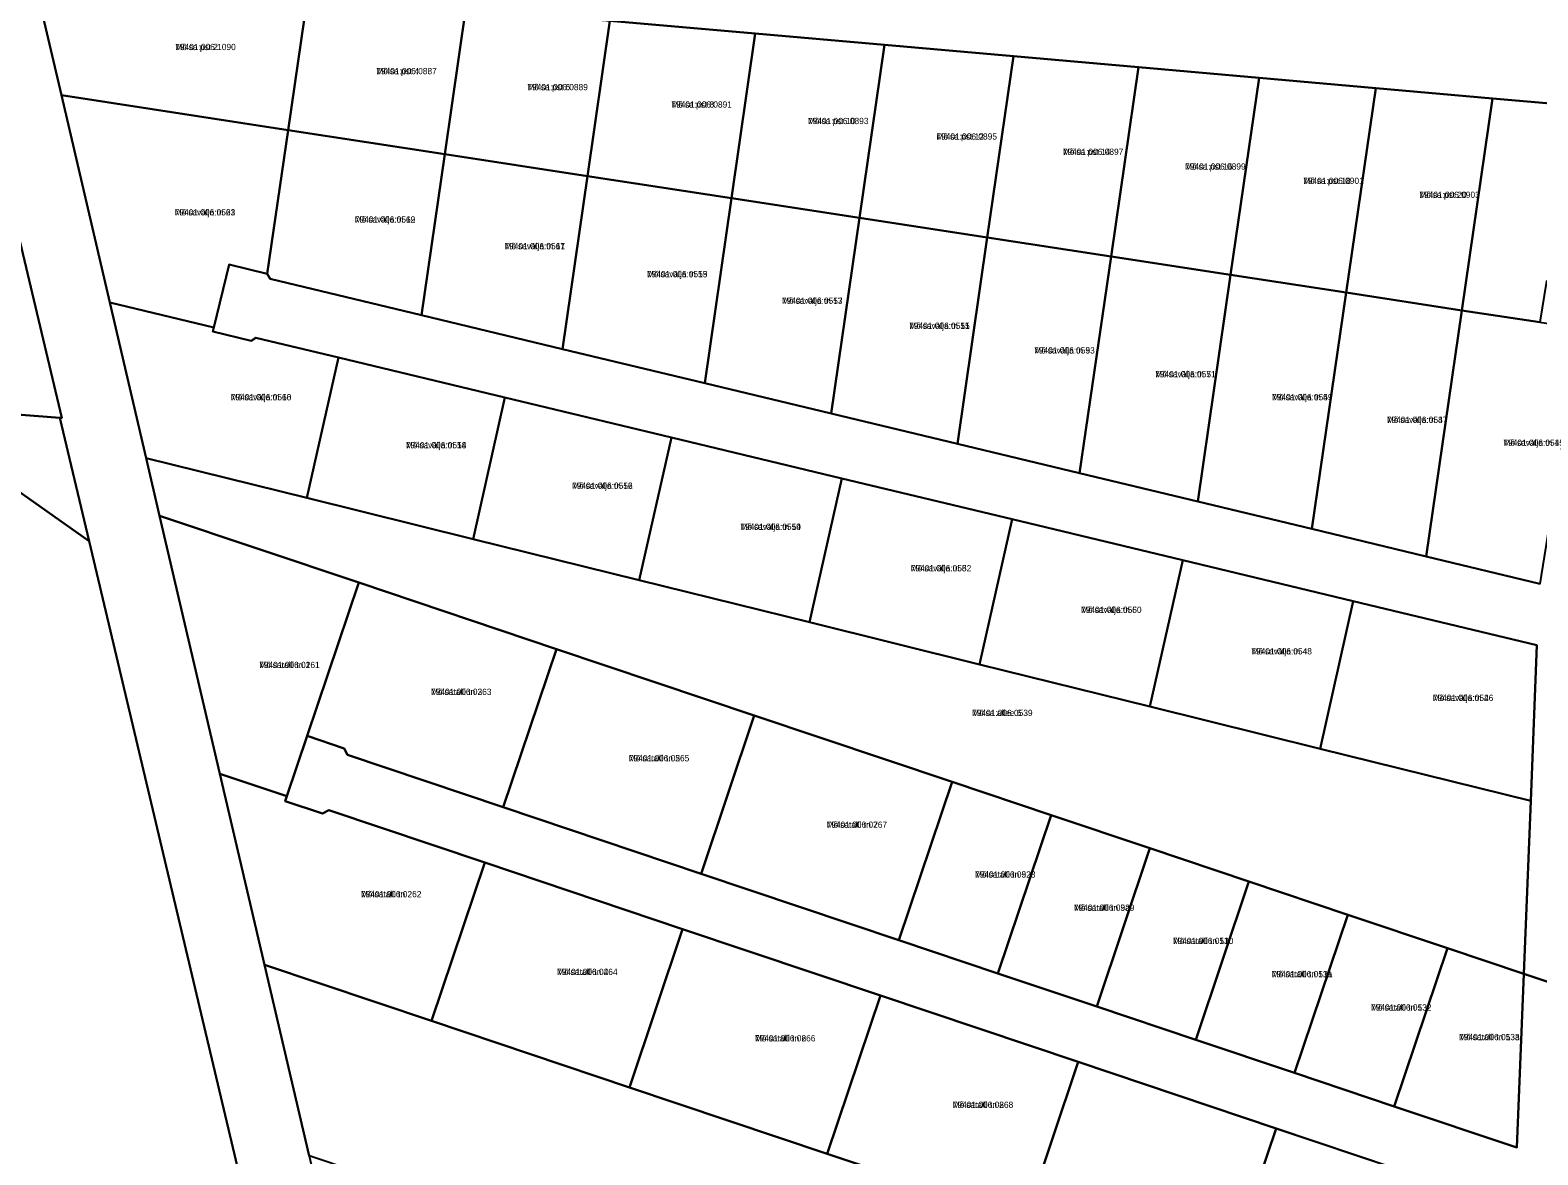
# Model space of a CAD drawing. Extents: x 625111 to 706696, y 6474150 to 6504223.
# Drawn here: x 659027.1 to 659388.4, y 6476981 to 6477250.5 of the extents above; entities that cross this region are included whole.
import ezdxf

# ---------------------------------------------------------------- set-up
doc = ezdxf.new("R2010")
doc.units = 0
for name, color, linetype in [('L_AADRESS', 7, 'Continuous'), ('PIIR', 7, 'Continuous'), ('TUNNUS', 7, 'Continuous')]:
    doc.layers.add(name, color=color, linetype=linetype)

msp = doc.modelspace()

# ---------------------------------------------------------------- linework, layer by layer
at = {"layer": 'PIIR'}
for points in [[(658929.46, 6477515.88), (658932.08, 6477516.4), (658982.24, 6477363.23), (658997.92, 6477309.95), (659008.22, 6477269.11), (659034.75, 6477157.58), (659034.25, 6477157.62), (659022.98, 6477158.48), (659018.49, 6477177.34), (659008.59, 6477218.73), (658996.7, 6477269.62), (658989.31, 6477301.21), (658978.46, 6477340.07), (658976.43, 6477347.36), (658971.21, 6477364.81), (658970.92, 6477365.75), (658960.91, 6477395.57), (658954.44, 6477414.91), (658943.03, 6477449.01), (658921.35, 6477514.3)], [(659093.63, 6477259.08), (659088.92, 6477226.55), (659034.62, 6477234.89), (659027.61, 6477264.87), (659060.39, 6477262)], [(659131.55, 6477255.75), (659126.48, 6477220.78), (659088.92, 6477226.55), (659093.63, 6477259.08)], [(659166.04, 6477252.72), (659160.66, 6477215.53), (659126.48, 6477220.78), (659131.55, 6477255.75)], [(659200.88, 6477249.65), (659195.17, 6477210.23), (659160.66, 6477215.53), (659166.04, 6477252.72)], [(659231.81, 6477246.94), (659225.81, 6477205.53), (659195.17, 6477210.23), (659200.88, 6477249.65)], [(659262.74, 6477244.22), (659256.45, 6477200.82), (659225.81, 6477205.53), (659231.81, 6477246.94)], [(659292.67, 6477241.59), (659286.11, 6477196.27), (659256.45, 6477200.82), (659262.74, 6477244.22)], [(659321.6, 6477239.04), (659314.77, 6477191.86), (659286.11, 6477196.27), (659292.67, 6477241.59)], [(659349.54, 6477236.59), (659342.45, 6477187.61), (659314.77, 6477191.86), (659321.6, 6477239.04)], [(659088.92, 6477226.55), (659083.94, 6477192.1), (659074.78, 6477194.31), (659071.17, 6477179.22), (659046.22, 6477185.21), (659034.62, 6477234.89)], [(659377.48, 6477234.13), (659370.13, 6477183.36), (659342.45, 6477187.61), (659349.54, 6477236.59)], [(659407.08, 6477231.53), (659400.24, 6477188.86), (659390.43, 6477190.36), (659388.85, 6477180.49), (659370.13, 6477183.36), (659377.48, 6477234.13)], [(659126.48, 6477220.78), (659120.9, 6477182.2), (659084.64, 6477190.9), (659083.94, 6477192.1), (659088.92, 6477226.55)], [(659160.66, 6477215.53), (659154.66, 6477174.09), (659120.9, 6477182.2), (659126.48, 6477220.78)], [(659195.17, 6477210.23), (659188.75, 6477165.91), (659154.66, 6477174.09), (659160.66, 6477215.53)], [(659225.81, 6477205.53), (659219.02, 6477158.64), (659188.75, 6477165.91), (659195.17, 6477210.23)], [(659256.45, 6477200.82), (659249.3, 6477151.38), (659219.02, 6477158.64), (659225.81, 6477205.53)], [(658404.01, 6477187.04), (658405.42, 6477203), (658447.18, 6477199.93), (658486.87, 6477196.96), (658527.12, 6477193.96), (658534.1, 6477193.43), (658545.15, 6477192.65), (658686.78, 6477182.82), (658692, 6477182.49), (658697.98, 6477182), (659022.98, 6477158.48), (659034.25, 6477157.62), (659041.31, 6477128.02), (659009.66, 6477150.34), (658694.91, 6477173.6), (658542.28, 6477178.48), (658526.7, 6477177.95)], [(659286.11, 6477196.27), (659278.59, 6477144.34), (659249.3, 6477151.38), (659256.45, 6477200.82)], [(659314.77, 6477191.86), (659306.91, 6477137.55), (659278.59, 6477144.34), (659286.11, 6477196.27)], [(659342.45, 6477187.61), (659334.25, 6477130.98), (659306.91, 6477137.55), (659314.77, 6477191.86)], [(659370.13, 6477183.36), (659361.59, 6477124.42), (659334.25, 6477130.98), (659342.45, 6477187.61)], [(659101.02, 6477172.06), (659093.46, 6477138.41), (659054.92, 6477147.94), (659046.22, 6477185.21), (659071.17, 6477179.22), (659070.94, 6477178.26), (659080.12, 6477176.09), (659081.22, 6477176.81)], [(659398.66, 6477178.98), (659388.87, 6477117.87), (659361.59, 6477124.42), (659370.13, 6477183.36), (659388.85, 6477180.49)], [(659140.89, 6477162.49), (659133.26, 6477128.56), (659093.46, 6477138.41), (659101.02, 6477172.06)], [(659180.76, 6477152.92), (659173.07, 6477118.71), (659133.26, 6477128.56), (659140.89, 6477162.49)], [(659221.6, 6477143.11), (659213.85, 6477108.61), (659173.07, 6477118.71), (659180.76, 6477152.92)], [(659386.69, 6477065.84), (659385.04, 6477024.38), (659366.7, 6477030.54), (659342.83, 6477038.56), (659319.13, 6477046.52), (659295.43, 6477054.47), (659271.73, 6477062.43), (659248.03, 6477070.39), (659200.63, 6477086.3), (659153.23, 6477102.22), (659105.87, 6477118.12), (659058.14, 6477134.15), (659054.92, 6477147.94), (659093.46, 6477138.41), (659133.26, 6477128.56), (659173.07, 6477118.71), (659213.85, 6477108.61), (659254.63, 6477098.52), (659295.41, 6477088.43), (659336.19, 6477078.34)], [(659262.45, 6477133.31), (659254.63, 6477098.52), (659213.85, 6477108.61), (659221.6, 6477143.11)], [(659105.87, 6477118.12), (659093.5, 6477081.41), (659088.6, 6477066.96), (659072.57, 6477072.34), (659058.14, 6477134.15)], [(659303.29, 6477123.5), (659295.41, 6477088.43), (659254.63, 6477098.52), (659262.45, 6477133.31)], [(659344.14, 6477113.7), (659336.19, 6477078.34), (659295.41, 6477088.43), (659303.29, 6477123.5)], [(659153.23, 6477102.22), (659140.5, 6477064.3), (659103.13, 6477076.85), (659102.39, 6477078.42), (659093.5, 6477081.41), (659105.87, 6477118.12)], [(659388.17, 6477103.13), (659386.69, 6477065.84), (659336.19, 6477078.34), (659344.14, 6477113.7)], [(659200.63, 6477086.3), (659187.9, 6477048.38), (659140.5, 6477064.3), (659153.23, 6477102.22)], [(659248.03, 6477070.39), (659235.3, 6477032.47), (659187.9, 6477048.38), (659200.63, 6477086.3)], [(659136.05, 6477051.03), (659123.31, 6477013.11), (659083.27, 6477026.56), (659072.57, 6477072.34), (659088.6, 6477066.96), (659088.21, 6477065.78), (659097.14, 6477062.77), (659098.67, 6477063.58)], [(659271.73, 6477062.43), (659259, 6477024.51), (659235.3, 6477032.47), (659248.03, 6477070.39)], [(659295.43, 6477054.47), (659282.7, 6477016.55), (659259, 6477024.51), (659271.73, 6477062.43)], [(659319.13, 6477046.52), (659306.4, 6477008.6), (659282.7, 6477016.55), (659295.43, 6477054.47)], [(659183.44, 6477035.11), (659170.71, 6476997.19), (659123.31, 6477013.11), (659136.05, 6477051.03)], [(659342.83, 6477038.56), (659330.1, 6477000.64), (659306.4, 6477008.6), (659319.13, 6477046.52)], [(659366.7, 6477030.54), (659353.98, 6476992.62), (659330.1, 6477000.64), (659342.83, 6477038.56)], [(659230.84, 6477019.2), (659218.11, 6476981.28), (659170.71, 6476997.19), (659183.44, 6477035.11)], [(659385.04, 6477024.38), (659383.31, 6476982.77), (659353.98, 6476992.62), (659366.7, 6477030.54)], [(659380.98, 6476926.59), (659379.26, 6476884.98), (659347.59, 6476895.61), (659300.18, 6476911.53), (659252.77, 6476927.45), (659205.37, 6476943.37), (659157.96, 6476959.28), (659093.96, 6476980.77), (659083.27, 6477026.56), (659123.31, 6477013.11), (659170.71, 6476997.19), (659218.11, 6476981.28), (659265.51, 6476965.36), (659312.91, 6476949.45)], [(659278.24, 6477003.28), (659265.51, 6476965.36), (659218.11, 6476981.28), (659230.84, 6477019.2)], [(659325.64, 6476987.37), (659312.91, 6476949.45), (659265.51, 6476965.36), (659278.24, 6477003.28)], [(659355.03, 6476977.5), (659342.3, 6476939.58), (659312.91, 6476949.45), (659325.64, 6476987.37)]]:
    msp.add_lwpolyline(points, close=True, dxfattribs=at)
for points in [[(659022.88, 6477285.14), (659027.61, 6477264.87), (659034.62, 6477234.89), (659046.22, 6477185.21), (659054.92, 6477147.94), (659058.14, 6477134.15), (659072.57, 6477072.34), (659083.27, 6477026.56), (659093.96, 6476980.77), (659119.09, 6476873.18), (659130.63, 6476823.75), (659145.22, 6476761.27), (659156.03, 6476714.99), (659137.78, 6476720.47), (659111.23, 6476832.81), (659041.31, 6477128.02), (659034.25, 6477157.62), (659034.75, 6477157.58), (659008.22, 6477269.11)], [(659407.08, 6477231.53), (659377.48, 6477234.13), (659349.54, 6477236.59), (659321.6, 6477239.04), (659292.67, 6477241.59), (659262.74, 6477244.22), (659231.81, 6477246.94), (659200.88, 6477249.65), (659166.04, 6477252.72), (659131.55, 6477255.75), (659093.63, 6477259.08), (659060.39, 6477262), (659062.43, 6477281.9), (659107.27, 6477277.96), (659152.1, 6477274.02), (659196.93, 6477270.08), (659241.76, 6477266.14), (659286.59, 6477262.2), (659331.43, 6477258.26), (659376.26, 6477254.32), (659410.25, 6477251.33)], [(659398.86, 6477019.74), (659385.04, 6477024.38), (659386.69, 6477065.84), (659388.17, 6477103.13), (659344.14, 6477113.7), (659303.29, 6477123.5), (659262.45, 6477133.31), (659221.6, 6477143.11), (659180.76, 6477152.92), (659140.89, 6477162.49), (659101.02, 6477172.06), (659081.22, 6477176.81), (659080.12, 6477176.09), (659070.94, 6477178.26), (659071.17, 6477179.22), (659074.78, 6477194.31), (659083.94, 6477192.1), (659084.64, 6477190.9), (659120.9, 6477182.2), (659154.66, 6477174.09), (659188.75, 6477165.91), (659219.02, 6477158.64), (659249.3, 6477151.38), (659278.59, 6477144.34), (659306.91, 6477137.55), (659334.25, 6477130.98), (659361.59, 6477124.42), (659388.87, 6477117.87)], [(659009.66, 6477150.34), (659041.31, 6477128.02), (659111.23, 6476832.81), (659086.38, 6476838.21), (659080.22, 6476839.48), (659049.44, 6476846.2), (659015.92, 6476853.56)], [(659382.71, 6476968.2), (659325.64, 6476987.37), (659278.24, 6477003.28), (659230.84, 6477019.2), (659183.44, 6477035.11), (659136.05, 6477051.03), (659098.67, 6477063.58), (659097.14, 6477062.77), (659088.21, 6477065.78), (659088.6, 6477066.96), (659093.5, 6477081.41), (659102.39, 6477078.42), (659103.13, 6477076.85), (659140.5, 6477064.3), (659187.9, 6477048.38), (659235.3, 6477032.47), (659259, 6477024.51), (659282.7, 6477016.55), (659306.4, 6477008.6), (659330.1, 6477000.64), (659353.98, 6476992.62), (659383.31, 6476982.77), (659385.04, 6477024.38), (659398.86, 6477019.74)]]:
    msp.add_lwpolyline(points, dxfattribs=at)

# ---------------------------------------------------------------- texts
at = {"layer": 'L_AADRESS'}
for s, p in [('Mõisa pst 2', (659061.89, 6477245.71)), ('Mõisa pst 4', (659110.06, 6477239.93)), ('Mõisa pst 6', (659146.26, 6477236.1)), ('Mõisa pst 8', (659180.77, 6477231.93)), ('Mõisa pst 10', (659213.49, 6477227.98)), ('Mõisa pst 12', (659244.28, 6477224.27)), ('Mõisa pst 14', (659274.56, 6477220.61)), ('Mõisa pst 16', (659303.86, 6477217.07)), ('Mõisa pst 18', (659332.16, 6477213.65)), ('Mõisa pst 20', (659359.96, 6477210.3)), ('Mõisavälja tn 21', (659061.77, 6477206.1)), ('Mõisavälja tn 19', (659104.91, 6477204.38)), ('Mõisavälja tn 17', (659140.78, 6477198)), ('Mõisavälja tn 15', (659174.91, 6477191.29)), ('Mõisavälja tn 13', (659207.28, 6477184.92)), ('Mõisavälja tn 11', (659237.74, 6477178.92)), ('Mõisavälja tn 9', (659267.7, 6477173.02)), ('Mõisavälja tn 7', (659296.68, 6477167.32)), ('Mõisavälja tn 16', (659075.2, 6477161.81)), ('Mõisavälja tn 5', (659324.68, 6477161.81)), ('Mõisavälja tn 3', (659352.19, 6477156.39)), ('Mõisavälja tn 14', (659117.14, 6477150.31)), ('Mõisavälja tn 1', (659380.12, 6477150.9)), ('Mõisavälja tn 12', (659156.98, 6477140.6)), ('Mõisavälja tn 10', (659197.3, 6477130.77)), ('Mõisavälja tn 8', (659238.12, 6477120.82)), ('Mõisavälja tn 6', (659278.93, 6477110.87)), ('Mõisavälja tn 4', (659319.74, 6477100.92)), ('Mõisatalli tn 1', (659082, 6477097.65)), ('Mõisatalli tn 3', (659123.17, 6477091.21)), ('Mõisavälja tn 2', (659363.2, 6477089.77)), ('Mõisa allee 6', (659252.82, 6477086.16)), ('Mõisatalli tn 5', (659170.56, 6477075.3)), ('Mõisatalli tn 7', (659217.96, 6477059.38)), ('Mõisatalli tn 9', (659253.51, 6477047.45)), ('Mõisatalli tn 2', (659106.38, 6477042.73)), ('Mõisatalli tn 9a', (659277.21, 6477039.49)), ('Mõisatalli tn 11', (659300.92, 6477031.53)), ('Mõisatalli tn 4', (659153.38, 6477024.11)), ('Mõisatalli tn 11a', (659324.61, 6477023.58)), ('Mõisatalli tn 13', (659348.4, 6477015.59)), ('Mõisatalli tn 6', (659200.78, 6477008.2)), ('Mõisatalli tn 13a', (659369.51, 6477008.5)), ('Mõisatalli tn 8', (659248.18, 6476992.28))]:
    msp.add_text(s, height=1.5, dxfattribs=at).set_placement(p)
at = {"layer": 'TUNNUS'}
for s, p in [('79401:006:1090', (659061.89, 6477245.71)), ('79401:006:0887', (659110.06, 6477239.93)), ('79401:006:0889', (659146.26, 6477236.1)), ('79401:006:0891', (659180.77, 6477231.93)), ('79401:006:0893', (659213.49, 6477227.98)), ('79401:006:0895', (659244.28, 6477224.27)), ('79401:006:0897', (659274.56, 6477220.61)), ('79401:006:0899', (659303.86, 6477217.07)), ('79401:006:0901', (659332.16, 6477213.65)), ('79401:006:0903', (659359.96, 6477210.3)), ('79401:006:0563', (659061.77, 6477206.1)), ('79401:006:0562', (659104.91, 6477204.38)), ('79401:006:0561', (659140.78, 6477198)), ('79401:006:0559', (659174.91, 6477191.29)), ('79401:006:0557', (659207.28, 6477184.92)), ('79401:006:0555', (659237.74, 6477178.92)), ('79401:006:0553', (659267.7, 6477173.02)), ('79401:006:0551', (659296.68, 6477167.32)), ('79401:006:0560', (659075.2, 6477161.81)), ('79401:006:0549', (659324.68, 6477161.81)), ('79401:006:0547', (659352.19, 6477156.39)), ('79401:006:0558', (659117.14, 6477150.31)), ('79401:006:0545', (659380.12, 6477150.9)), ('79401:006:0556', (659156.98, 6477140.6)), ('79401:006:0554', (659197.3, 6477130.77)), ('79401:006:0552', (659238.12, 6477120.82)), ('79401:006:0550', (659278.93, 6477110.87)), ('79401:006:0548', (659319.74, 6477100.92)), ('79401:006:0261', (659082, 6477097.65)), ('79401:006:0263', (659123.17, 6477091.21)), ('79401:006:0546', (659363.2, 6477089.77)), ('79401:006:0539', (659252.82, 6477086.16)), ('79401:006:0265', (659170.56, 6477075.3)), ('79401:006:0267', (659217.96, 6477059.38)), ('79401:006:0528', (659253.51, 6477047.45)), ('79401:006:0262', (659106.38, 6477042.73)), ('79401:006:0529', (659277.21, 6477039.49)), ('79401:006:0530', (659300.92, 6477031.53)), ('79401:006:0264', (659153.38, 6477024.11)), ('79401:006:0531', (659324.61, 6477023.58)), ('79401:006:0532', (659348.4, 6477015.59)), ('79401:006:0266', (659200.78, 6477008.2)), ('79401:006:0533', (659369.51, 6477008.5)), ('79401:006:0268', (659248.18, 6476992.28))]:
    msp.add_text(s, height=1.5, dxfattribs=at).set_placement(p)

doc.saveas('drawing.dxf')
